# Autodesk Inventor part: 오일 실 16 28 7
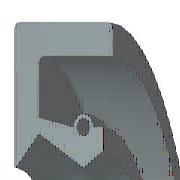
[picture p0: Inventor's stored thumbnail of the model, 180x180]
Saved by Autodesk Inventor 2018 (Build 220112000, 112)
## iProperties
Created: 2012-02
Part Number: 오일 실 16 28 7
Material: 고무
Description: 오일-실
Document SubType Name: Modeling
Standard: KS B 2804
Designer: mduedu
Standards Organization: KS
Language: ko-KR
Size Designation: D - 16 28 7
Categories: <MemberInstance><Categories><Category DisplayName="샤프트 부품" InternalName="7f7aeb1f-a693-4053-b835-cee3144e0d98" Mnemonic="SHFT"><Category DisplayName="실링" Intern
Density: 0.93 g/cm^3
Appearance: 고무 - 검은색 - 버전 1.1
IsCustomPart: 1
Author: mduedu
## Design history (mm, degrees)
revolve "본체" stored, may be unused: angle "d17" = 90 deg
revolve "스프링1" stored, may be unused: angle "d18" = 90 deg
fillet "모깎기3" dims "d43" = 0.5
body "Solid1"
sketch "스케치1"
  geometry: L1 (0, 14)-(7, 14); L2 (7, 12.25)-(1.75, 12.25); L3 (1.75, 9.75)-(4.9, 8); L4 (4.9, 8)-(0, 8); L5 (0, 0)-(9.586, 0) reference; L6 (4.9, 8)-(6.3, 8.875); L7 (0, 18)-(0, -3) reference; L8 (-1.941, 0)-(11.507, 0) reference; L9 (4.2, 10.1)-(1.75, 10.59); L10 (1.75, 10.59)-(1.75, 12.25); L11 (0, 14)-(0, 8.088); L12 (4.9, 8)-(0, 8); L13 (1.75, 9.75)-(0.152, 8.028); L14 (7, 14)-(7, 12.25); L15 (5.6, 10.1)-(6.3, 10.1); L16 (6.3, 10.1)-(6.3, 8.875); C1 r 0.455 at (4.9, 10.1); A1 r 0.7 centre (4.9, 10.1) between (5.6, 10.1) and (4.2, 10.1); A2 r 0.088 centre (0.088, 8.088) between (0, 8.088) and (0.152, 8.028); 1 further point
  constraints: 28 end point, 5 horizontal alignment, 5 point on line, 4 point on circle, 4 vertical alignment, 3 centre point, 3 tangent, 2 collinear, 2 horizontal, 2 perpendicular, 1 coincident, 1 parallel
  dimensions: "d0" = 28 diameter of L1 L5 (= SD2); "d1" = 1.75 distance of L1.end L2.start (= SD); "d2" = 0.91 diameter of C1 (= SPDI); "d3" = 1.4 diameter of A1 (= SPDA); "d4" = 16 diameter of L3.end L5 (= NND); "d5" = 19.5 diameter of L3.start L5 (= TKDM); "d7" = 21.18 diameter of L9.end L5 (= TKDM + 0.24 x SWDT); "d8" = 1.75 distance between parallel lines of L11 L10 (= SD); "d9" = 4.9 distance from line of L11 C1.centre (= SPDST); "d10" = 20.2 diameter of C1.centre L5 (= HLDM); "d11" = 0.0875 radius of A2 (= 0.25 x LAB); "d12" = 6.3 distance between parallel lines of L11 L16 (= SDI); "d13" = 17.75 diameter of L6.end L5 (= ABDM); "d14" = 7 distance from line of L11 L1.end (= SWDT)
fillet "모깎기1" dims "d6" = 0.3 (= RR)
other parameters: "SD2" = 28 [user parameter; used in 1 equation term], "SWDT" = 7 [user parameter; used in 2 equation terms], "RR" = 0.3 [user parameter; used in 1 equation term], "SD" = 1.75 [user parameter; used in 2 equation terms], "NND" = 16 [user parameter; used in 1 equation term], "SPDA" = 1.4 [user parameter; used in 1 equation term], "SPDI" = 0.91 [user parameter; used in 1 equation term], "TKDM" = 19.5 [user parameter; used in 2 equation terms], "HLDM" = 20.2 [user parameter; used in 1 equation term], "ABDM" = 17.75 [user parameter; used in 1 equation term], "SDI" = 6.3 [user parameter; used in 1 equation term], "SPDST" = 4.9 [user parameter; used in 1 equation term], "LAB" = 0.35 [user parameter; used in 1 equation term], "d15" = 0, "d16" = 0, "d19" = 0
